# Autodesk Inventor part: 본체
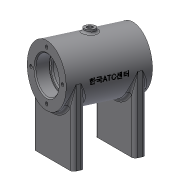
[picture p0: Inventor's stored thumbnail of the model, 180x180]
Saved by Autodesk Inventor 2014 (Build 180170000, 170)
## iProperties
Created: 2020-07
Part Number: 본체
Material: Generic
Document SubType Name: Modeling
Designer: kh
Density: 1 g/cm^3
Appearance: Default
Mass: 113.054 g
Surface Area: 357.567 cm^2
Volume: 113.054 cm^3
Author: kh
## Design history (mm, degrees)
sketch "Sketch1"
  geometry: C1 r 26 at (0, 64); 1 further point
  constraints: 1 centre point, 1 vertical alignment
  dimensions: "d0" = 64 distance of point (0, 0) C1.centre; "d5" = 52 diameter of C1
extrude "Extrusion1" new body sketch "Sketch1" stored distance "d1" = 70; taper "d2" = 0 deg
workplane "Work Plane1"
sketch "Sketch2"
  geometry: L1 (-26, -64)-(26, -64); L2 (-26, -64)-(-26, 0); L3 (26, -64)-(26, 0); A1 r 26 centre (0, 0) between (-26, 0) and (26, 0) reference; 2 further points
  constraints: 6 end point, 2 point on circle, 2 tangent, 1 coincident, 1 horizontal, 1 midpoint
  dimensions: "d4" = 52 distance of L1.start L1.end
extrude "Extrusion2" join sketch "Sketch2" distance "d6" = 10; taper "d7" = 0 deg
mirror "Mirror1"
sketch "Sketch3"
  geometry: L1 (90, 35)-(38, 35) reference; L2 (90, -35)-(90, 35) reference; L3 (38, -35)-(90, -35) reference; L4 (64, 35)-(64, -35); L5 (80, 35)-(80, 23.3); L6 (79.7, 23)-(78, 23); L7 (78, 23)-(78, 21); L8 (78, 21)-(82, 21); L9 (85, 18)-(85, -18); L10 (82, -21)-(78, -21); L11 (78, -21)-(78, -23); L12 (78, -23)-(79.7, -23); L13 (80, -23.3)-(80, -35); A1 r 0.3 centre (79.7, 23.3) between (79.7, 23) and (80, 23.3); A2 r 0.3 centre (79.7, -23.3) between (80, -23.3) and (79.7, -23); A3 r 3 centre (82, 18) between (85, 18) and (82, 21); A4 r 3 centre (82, -18) between (82, -21) and (85, -18); 5 further points
  constraints: 20 end point, 10 point on line, 8 point on circle, 8 tangent, 5 parallel, 4 centre point, 3 perpendicular, 2 equal radius, 2 midpoint, 1 collinear
  dimensions: "d8" = 32 diameter of L5 L4; "d9" = 28 diameter of L7 L4; "d10" = 42 diameter of L9 L4; "d11" = 28 diameter of L11 L4; "d12" = 32 diameter of L13 L4; "d13" = 12 distance of L5.start point (80, 23); "d14" = 42 distance of point (85, 21) point (85, -21); "d15" = 12 distance of point (80, -23) L13.end; "d16" = 2 distance of L6.end L7.end; "d17" = 0.3 radius of A1; "d18" = 3 radius of A3
revolve "Revolution1" sketch "Sketch3" stored, may be unused: angle "d19" = 90 deg
workplane "Work Plane3"
  workplane "Work Plane2"
sketch "Sketch4"
  geometry: C1 r 5 at (0, 0); 1 further point
  constraints: 1 centre point, 1 coincident
  dimensions: "d21" = 10 diameter of C1
extrude "Extrusion3" join sketch "Sketch4" stored distance "d22" = 10; taper "d23" = 0 deg
hole "Hole1" diameter "d26" = 5.188; stored, may be unused: countersink angle "d30" = 90 deg, drill point angle "d32" = 118 deg; dims "d24" = 10, "d25" = 10, "d27" = 6, "d28" = 4, "d29" = 2, "d31" = 19.25
sketch "Sketch5"
  geometry: L1 (0, 64)-(9.919, 36.749); L2 (0, 64)-(0, 29.46); L3 (14.291, 42.28)-(15.557, 38.801); L4 (9.919, 36.749)-(15.557, 38.801); L5 (9.919, 36.749)-(8.893, 39.568); C1 r 26 at (0, 64) reference; A1 r 26 centre (0, 64) between (8.893, 39.568) and (14.291, 42.28); 1 further point
  constraints: 10 end point, 2 point on circle, 1 centre point, 1 coincident, 1 parallel, 1 perpendicular, 1 point on line, 1 vertical
  dimensions: "d35" = 29 distance of L1.start L1.end; "d36" = 20 deg angle of L1 L2; "d37" = 6 distance between parallel lines of L3 L1
revolve "Revolution2" sketch "Sketch5" stored, may be unused: angle "d38" = 90 deg
hole "Hole2" diameter "d41" = 5.188; stored, may be unused: countersink angle "d45" = 90 deg, drill point angle "d47" = 118 deg; dims "d39" = 10, "d40" = 10, "d42" = 6, "d43" = 4, "d44" = 2, "d46" = 19.25
sketch "Sketch6"
  geometry: C1 r 16 at (0, 0) reference; 2 further points
  constraints: 1 vertical alignment
  dimensions: "d48" = 21 distance of C1.centre point (0, 21)
hole "Hole3" sketch "Sketch6" at (0, 21) diameter "d49" = 3.242; stored, may be unused: countersink angle "d53" = 90 deg, drill point angle "d55" = 118 deg; dims "d50" = 8, "d51" = 4, "d52" = 2, "d54" = 10
pattern_circular "Circular Pattern1" dims angle "d57" = 360 deg
mirror "Mirror2"
sketch "Sketch7"
  geometry: L1 (0, 0)-(52, 0) reference; L2 (52, 0)-(52, -10) reference; 3 further points
  constraints: 1 horizontal alignment
  dimensions: "d59" = 5 distance from line of point (6, -5) L1; "d60" = 40 distance of point (6, -5) point (46, -5); "d61" = 6 distance from line of L2 point (46, -5)
hole "Hole4" sketch "Sketch7" at (6, -5), (46, -5) diameter "d62" = 4.134; stored, may be unused: countersink angle "d66" = 90 deg, drill point angle "d68" = 118 deg; dims "d63" = 8, "d64" = 4, "d65" = 2, "d67" = 10
mirror "Mirror3"
chamfer "Chamfer1" distance "d69" = 1; stored, may be unused: second distance "d70" = 2, angle "d71" = 45 deg
fillet "Fillet1" dims "d72" = 2
fillet "Fillet2" dims "d73" = 3
fillet "Fillet3" dims "d74" = 3
workplane "Work Plane4"
sketch "Sketch8"
  geometry: L1 (-26, -35)-(26, -35) reference; L2 (-26, -35)-(-26, 35) reference; 2 further points
  constraints: 1 other
  dimensions: "d75" = 35 distance from line of point (0, 0) L1; "d76" = 26 distance from line of point (0, 0) L2
emboss "Emboss1" sketch "Sketch8" dims "d1" = 70, "d2" = 0, "d8" = 32, "d9" = 28, "d10" = 42, "d11" = 28, "d12" = 32, "d13" = 12, "d14" = 42, "d15" = 12, "d16" = 2, "d17" = 0.3, "d18" = 3, "d77" = 0.5, "d78" = 0
body "Solid1"
node "Projected Loop1"
other parameters: "d3" = -5, "d20" = 3
